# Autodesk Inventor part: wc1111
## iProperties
Shininess: 64.0
Length Units: 11272
Angle Units: 11279
Time Units: 11290
Mass Units: 11286
Length Display Precision: 3
Angle Display Precision: 2
Compacted: True
Part Number: wc1111
Document SubType Name: Modeling
Created: 2004-08
Designer: John Blackburn
Manufacturer: Standard
Standards Organization: Custom
Density: 0.0
Volumn: 0.0
Area: 0.0
PropertySet Name: Model Information
Control State: 0
Master: False
Checked Out: False
Author: John Blackburn
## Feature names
1. Base1
